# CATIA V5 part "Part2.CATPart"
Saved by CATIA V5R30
Part number: Part2
Bounding box of the stored display mesh (mm): x -29.913 to 29.913, y -29.913 to 29.913, z -89.119 to 0
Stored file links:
  D:\PROJECTS\CATIA V56R 2020\Resources\Parts File\c12_catia_v5_6r2020_prt\c12_catia_v5-6r2020 figr_12-35\Part2.CATPart
  C:\CATIA-V5R13-manuscript\catia-v5r13-solid-models-090204\c11\Figure 11-35\Figure 11-35.CATProduct
  D:\PROJECTS\CATIA V56R 2020\Resources\Parts File\c12_catia_v5_6r2020_prt\c12_catia_v5-6r2020 figr_12-35\Base.CATPart
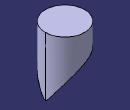
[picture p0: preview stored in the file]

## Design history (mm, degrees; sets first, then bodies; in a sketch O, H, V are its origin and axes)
Set1
  DatumSurface1: linked copy from another document
Body1 (main body)
  Sketch1 on xy-plane, origin (0, 0, 0), H (1, 0, 0), V (0, 1, 0)
    circle A1 centre (0, 0) radius 29.9132
  Pad1: profile Sketch1, direction (0, 0, 1), up to face of DatumSurface1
